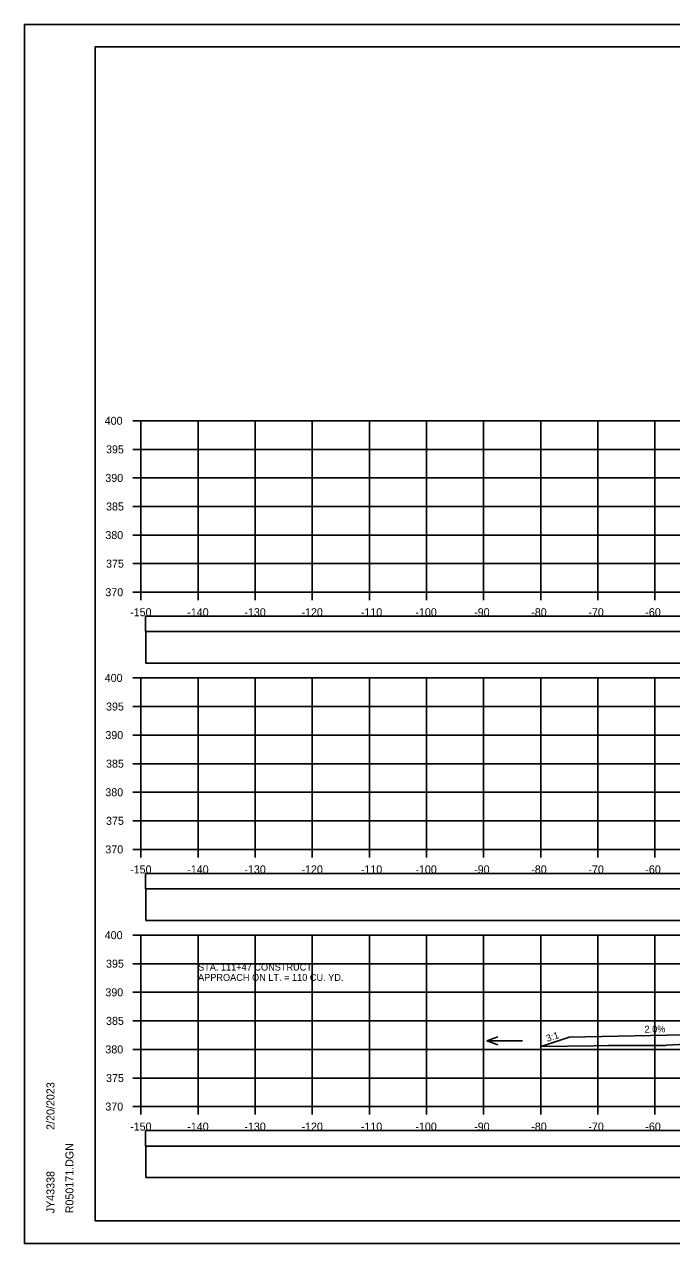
# Model space of a CAD drawing. Extents: x -37291014 to -37290680, y -936053 to -933067.
# Drawn here: x -37291013.5 to -37290900.2, y -933706.6 to -933493.3 of the extents above; entities that cross this region are included whole.
import ezdxf

# ---------------------------------------------------------------- set-up
doc = ezdxf.new("R2010")
doc.units = 0
for name, color, linetype in [('Default', 7, 'Continuous'), ('R_Axis', 7, 'Continuous'), ('R_Axis Annot', 7, 'Continuous'), ('R_Border', 7, 'Continuous'), ('R_Drive', 7, 'Continuous'), ('R_Exist Surface', 7, 'Continuous'), ('R_Grid', 7, 'Continuous'), ('R_No Plot', 7, 'Continuous'), ('R_Water Annot', 7, 'Continuous'), ('R_Xsect Elev', 7, 'Continuous')]:
    doc.layers.add(name, color=color, linetype=linetype)

msp = doc.modelspace()

# ---------------------------------------------------------------- linework, layer by layer
at = {"layer": 'Default'}
for points in [[(-37290992.31, -933599.51), (-37290693.89, -933599.51), (-37290693.89, -933596.81), (-37290992.31, -933596.81)], [(-37290992.26, -933605.03), (-37290693.84, -933605.03), (-37290693.84, -933599.51), (-37290992.26, -933599.51)], [(-37290992.31, -933644.51), (-37290693.89, -933644.51), (-37290693.89, -933641.81), (-37290992.31, -933641.81)], [(-37290992.26, -933650.03), (-37290693.84, -933650.03), (-37290693.84, -933644.51), (-37290992.26, -933644.51)], [(-37290992.31, -933689.51), (-37290693.89, -933689.51), (-37290693.89, -933686.81), (-37290992.31, -933686.81)], [(-37290992.26, -933695.03), (-37290693.84, -933695.03), (-37290693.84, -933689.51), (-37290992.26, -933689.51)]]:
    msp.add_lwpolyline(points, close=True, dxfattribs=at)
at = {"layer": 'R_Axis'}
for p, q in [((-37290994.5, -933562.61), (-37290993.1, -933562.61)), ((-37290993.1, -933592.61), (-37290993.1, -933562.61)), ((-37290994.5, -933567.61), (-37290993.1, -933567.61)), ((-37290994.5, -933572.61), (-37290993.1, -933572.61)), ((-37290994.5, -933577.61), (-37290993.1, -933577.61)), ((-37290994.5, -933582.61), (-37290993.1, -933582.61)), ((-37290994.5, -933587.61), (-37290993.1, -933587.61)), ((-37290994.5, -933592.61), (-37290993.1, -933592.61)), ((-37290993.1, -933592.61), (-37290693.1, -933592.61)), ((-37290993.1, -933594.01), (-37290993.1, -933592.61)), ((-37290983.1, -933594.01), (-37290983.1, -933592.61)), ((-37290973.1, -933594.01), (-37290973.1, -933592.61)), ((-37290963.1, -933594.01), (-37290963.1, -933592.61)), ((-37290953.1, -933594.01), (-37290953.1, -933592.61)), ((-37290943.1, -933594.01), (-37290943.1, -933592.61)), ((-37290933.1, -933594.01), (-37290933.1, -933592.61)), ((-37290923.1, -933594.01), (-37290923.1, -933592.61)), ((-37290913.1, -933594.01), (-37290913.1, -933592.61)), ((-37290903.1, -933594.01), (-37290903.1, -933592.61)), ((-37290994.5, -933607.61), (-37290993.1, -933607.61)), ((-37290993.1, -933637.61), (-37290993.1, -933607.61)), ((-37290994.5, -933612.61), (-37290993.1, -933612.61)), ((-37290994.5, -933617.61), (-37290993.1, -933617.61)), ((-37290994.5, -933622.61), (-37290993.1, -933622.61)), ((-37290994.5, -933627.61), (-37290993.1, -933627.61)), ((-37290994.5, -933632.61), (-37290993.1, -933632.61)), ((-37290994.5, -933637.61), (-37290993.1, -933637.61)), ((-37290993.1, -933637.61), (-37290693.1, -933637.61)), ((-37290993.1, -933639.01), (-37290993.1, -933637.61)), ((-37290983.1, -933639.01), (-37290983.1, -933637.61)), ((-37290973.1, -933639.01), (-37290973.1, -933637.61)), ((-37290963.1, -933639.01), (-37290963.1, -933637.61)), ((-37290953.1, -933639.01), (-37290953.1, -933637.61)), ((-37290943.1, -933639.01), (-37290943.1, -933637.61)), ((-37290933.1, -933639.01), (-37290933.1, -933637.61)), ((-37290923.1, -933639.01), (-37290923.1, -933637.61)), ((-37290913.1, -933639.01), (-37290913.1, -933637.61)), ((-37290903.1, -933639.01), (-37290903.1, -933637.61)), ((-37290994.5, -933652.61), (-37290993.1, -933652.61)), ((-37290993.1, -933682.61), (-37290993.1, -933652.61)), ((-37290994.5, -933657.61), (-37290993.1, -933657.61)), ((-37290994.5, -933662.61), (-37290993.1, -933662.61)), ((-37290994.5, -933667.61), (-37290993.1, -933667.61)), ((-37290994.5, -933672.61), (-37290993.1, -933672.61)), ((-37290994.5, -933677.61), (-37290993.1, -933677.61)), ((-37290994.5, -933682.61), (-37290993.1, -933682.61)), ((-37290993.1, -933682.61), (-37290693.1, -933682.61)), ((-37290993.1, -933684.01), (-37290993.1, -933682.61)), ((-37290983.1, -933684.01), (-37290983.1, -933682.61)), ((-37290973.1, -933684.01), (-37290973.1, -933682.61)), ((-37290963.1, -933684.01), (-37290963.1, -933682.61)), ((-37290953.1, -933684.01), (-37290953.1, -933682.61)), ((-37290943.1, -933684.01), (-37290943.1, -933682.61)), ((-37290933.1, -933684.01), (-37290933.1, -933682.61)), ((-37290923.1, -933684.01), (-37290923.1, -933682.61)), ((-37290913.1, -933684.01), (-37290913.1, -933682.61)), ((-37290903.1, -933684.01), (-37290903.1, -933682.61))]:
    msp.add_line(p, q, dxfattribs=at)
at = {"layer": 'R_Border'}
for p, q in [((-37291001.1, -933497.15), (-37290684.92, -933497.15)), ((-37291001.1, -933702.61), (-37291001.1, -933497.15)), ((-37291001.1, -933702.61), (-37291001.1, -933702.61)), ((-37290684.92, -933702.61), (-37291001.1, -933702.61))]:
    msp.add_line(p, q, dxfattribs=at)
at = {"layer": 'R_Drive'}
for p, q in [((-37290888.1, -933669.85), (-37290918.1, -933670.45)), ((-37290918.1, -933670.45), (-37290923.05, -933672.1))]:
    msp.add_line(p, q, dxfattribs=at)
at = {"layer": 'R_Exist Surface'}
msp.add_line((-37290923.05, -933672.1), (-37290913.74, -933671.96), dxfattribs=at)
msp.add_lwpolyline([(-37290913.74, -933671.96), (-37290911.28, -933671.92), (-37290901.47, -933671.93), (-37290901.4, -933671.92), (-37290901.3, -933671.91), (-37290901.02, -933671.88), (-37290888.83, -933671.22)], dxfattribs=at)
at = {"layer": 'R_Grid'}
for p, q in [((-37290993.1, -933562.61), (-37290693.1, -933562.61)), ((-37290993.1, -933592.61), (-37290993.1, -933562.61)), ((-37290983.1, -933592.61), (-37290983.1, -933562.61)), ((-37290973.1, -933592.61), (-37290973.1, -933562.61)), ((-37290963.1, -933592.61), (-37290963.1, -933562.61)), ((-37290953.1, -933592.61), (-37290953.1, -933562.61)), ((-37290943.1, -933592.61), (-37290943.1, -933562.61)), ((-37290933.1, -933592.61), (-37290933.1, -933562.61)), ((-37290923.1, -933592.61), (-37290923.1, -933562.61)), ((-37290913.1, -933592.61), (-37290913.1, -933562.61)), ((-37290903.1, -933592.61), (-37290903.1, -933562.61)), ((-37290993.1, -933567.61), (-37290693.1, -933567.61)), ((-37290993.1, -933572.61), (-37290693.1, -933572.61)), ((-37290993.1, -933577.61), (-37290693.1, -933577.61)), ((-37290993.1, -933582.61), (-37290693.1, -933582.61)), ((-37290993.1, -933587.61), (-37290693.1, -933587.61)), ((-37290993.1, -933592.61), (-37290693.1, -933592.61)), ((-37290993.1, -933607.61), (-37290693.1, -933607.61)), ((-37290993.1, -933637.61), (-37290993.1, -933607.61)), ((-37290983.1, -933637.61), (-37290983.1, -933607.61)), ((-37290973.1, -933637.61), (-37290973.1, -933607.61)), ((-37290963.1, -933637.61), (-37290963.1, -933607.61)), ((-37290953.1, -933637.61), (-37290953.1, -933607.61)), ((-37290943.1, -933637.61), (-37290943.1, -933607.61)), ((-37290933.1, -933637.61), (-37290933.1, -933607.61)), ((-37290923.1, -933637.61), (-37290923.1, -933607.61)), ((-37290913.1, -933637.61), (-37290913.1, -933607.61)), ((-37290903.1, -933637.61), (-37290903.1, -933607.61)), ((-37290993.1, -933612.61), (-37290693.1, -933612.61)), ((-37290993.1, -933617.61), (-37290693.1, -933617.61)), ((-37290993.1, -933622.61), (-37290693.1, -933622.61)), ((-37290993.1, -933627.61), (-37290693.1, -933627.61)), ((-37290993.1, -933632.61), (-37290693.1, -933632.61)), ((-37290993.1, -933637.61), (-37290693.1, -933637.61)), ((-37290993.1, -933652.61), (-37290693.1, -933652.61)), ((-37290993.1, -933682.61), (-37290993.1, -933652.61)), ((-37290983.1, -933682.61), (-37290983.1, -933652.61)), ((-37290973.1, -933682.61), (-37290973.1, -933652.61)), ((-37290963.1, -933682.61), (-37290963.1, -933652.61)), ((-37290953.1, -933682.61), (-37290953.1, -933652.61)), ((-37290943.1, -933682.61), (-37290943.1, -933652.61)), ((-37290933.1, -933682.61), (-37290933.1, -933652.61)), ((-37290923.1, -933682.61), (-37290923.1, -933652.61)), ((-37290913.1, -933682.61), (-37290913.1, -933652.61)), ((-37290903.1, -933682.61), (-37290903.1, -933652.61)), ((-37290993.1, -933657.61), (-37290693.1, -933657.61)), ((-37290993.1, -933662.61), (-37290693.1, -933662.61)), ((-37290993.1, -933667.61), (-37290693.1, -933667.61)), ((-37290993.1, -933672.61), (-37290693.1, -933672.61)), ((-37290993.1, -933677.61), (-37290693.1, -933677.61)), ((-37290993.1, -933682.61), (-37290693.1, -933682.61))]:
    msp.add_line(p, q, dxfattribs=at)
at = {"layer": 'R_No Plot'}
for p, q in [((-37291013.5, -933493.25), (-37290680.17, -933493.25)), ((-37291013.5, -933706.58), (-37290680.17, -933706.58))]:
    msp.add_line(p, q, dxfattribs=at)
for points in [[(-37291013.51, -933493.25), (-37290680.17, -933493.25), (-37290680.17, -933706.59), (-37291013.51, -933706.59)], [(-37290767.18, -933497.15), (-37290747.56, -933497.15), (-37290747.56, -933507.03), (-37290731.45, -933507.03), (-37290708.25, -933507.03), (-37290708.25, -933531.36), (-37290684.92, -933531.36), (-37290684.92, -933702.61), (-37291001.1, -933702.61), (-37291001.1, -933497.15)]]:
    msp.add_lwpolyline(points, close=True, dxfattribs=at)
at = {"layer": 'R_Water Annot'}
for p, q in [((-37290932.55, -933671.09), (-37290930.63, -933670.39)), ((-37290926.27, -933671.09), (-37290932.55, -933671.09)), ((-37290932.55, -933671.09), (-37290930.63, -933671.79))]:
    msp.add_line(p, q, dxfattribs=at)

# ---------------------------------------------------------------- texts
at = {"layer": 'R_Axis Annot'}
for s, p in [('400', (-37290999.44, -933563.31)), ('395', (-37290999.21, -933568.31)), ('390', (-37290999.33, -933573.31)), ('385', (-37290999.21, -933578.31)), ('380', (-37290999.33, -933583.31)), ('375', (-37290999.21, -933588.31)), ('370', (-37290999.33, -933593.31)), ('-150', (-37290994.99, -933596.81)), ('-140', (-37290984.99, -933596.81)), ('-130', (-37290974.99, -933596.81)), ('-120', (-37290964.99, -933596.81)), ('-110', (-37290954.6, -933596.81)), ('-100', (-37290945.05, -933596.81)), ('-90', (-37290934.76, -933596.81)), ('-80', (-37290924.76, -933596.81)), ('-70', (-37290914.76, -933596.81)), ('-60', (-37290904.79, -933596.81)), ('400', (-37290999.44, -933608.31)), ('395', (-37290999.21, -933613.31)), ('390', (-37290999.33, -933618.31)), ('385', (-37290999.21, -933623.31)), ('380', (-37290999.33, -933628.31)), ('375', (-37290999.21, -933633.31)), ('370', (-37290999.33, -933638.31)), ('-150', (-37290994.99, -933641.81)), ('-140', (-37290984.99, -933641.81)), ('-130', (-37290974.99, -933641.81)), ('-120', (-37290964.99, -933641.81)), ('-110', (-37290954.6, -933641.81)), ('-100', (-37290945.05, -933641.81)), ('-90', (-37290934.76, -933641.81)), ('-80', (-37290924.76, -933641.81)), ('-70', (-37290914.76, -933641.81)), ('-60', (-37290904.79, -933641.81)), ('400', (-37290999.44, -933653.31)), ('395', (-37290999.21, -933658.31)), ('390', (-37290999.33, -933663.31)), ('385', (-37290999.21, -933668.31)), ('380', (-37290999.33, -933673.31)), ('375', (-37290999.21, -933678.31)), ('370', (-37290999.33, -933683.31)), ('-150', (-37290994.99, -933686.81)), ('-140', (-37290984.99, -933686.81)), ('-130', (-37290974.99, -933686.81)), ('-120', (-37290964.99, -933686.81)), ('-110', (-37290954.6, -933686.81)), ('-100', (-37290945.05, -933686.81)), ('-90', (-37290934.76, -933686.81)), ('-80', (-37290924.76, -933686.81)), ('-70', (-37290914.76, -933686.81)), ('-60', (-37290904.79, -933686.81))]:
    msp.add_text(s, height=1.4, dxfattribs=at).set_placement(p)
at = {"layer": 'R_Border'}
for s, p in [('2/20/2023', (-37291008.24, -933686.68)), ('R050171.DGN', (-37291004.91, -933701.28)), ('JY43338', (-37291008.24, -933701.28))]:
    msp.add_text(s, height=1.4, rotation=90, dxfattribs=at).set_placement(p)
at = {"layer": 'R_Water Annot'}
for s, p in [('APPROACH ON LT. = 110 CU. YD.', (-37290983.1, -933660.61)), ('STA. 111+47 CONSTRUCT', (-37290983.1, -933658.81))]:
    msp.add_text(s, height=1.2, dxfattribs=at).set_placement(p)
at = {"layer": 'R_Xsect Elev'}
for s, rotation, p in [('3:1', 18.4349, (-37290921.93, -933671.3)), ('2.0%', 1.1458, (-37290904.92, -933669.69))]:
    msp.add_text(s, height=1.2, rotation=rotation, dxfattribs=at).set_placement(p)

doc.saveas('drawing.dxf')
